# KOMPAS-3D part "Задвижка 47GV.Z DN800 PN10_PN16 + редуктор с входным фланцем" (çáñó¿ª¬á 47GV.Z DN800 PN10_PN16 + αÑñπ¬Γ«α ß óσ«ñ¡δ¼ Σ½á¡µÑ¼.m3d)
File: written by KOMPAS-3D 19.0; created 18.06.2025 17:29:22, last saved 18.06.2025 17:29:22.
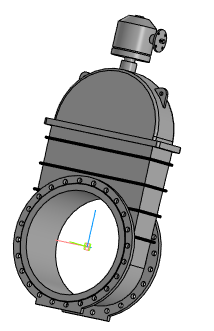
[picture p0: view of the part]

Document properties: Полное имя файла: Задвижка 47GV.Z DN800 PN10_PN16 + редуктор с входным валом.a3d

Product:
- Part/product: Задвижка 47GV.Z DN800 PN10_PN16 + редуктор с входным фланцем
    Масса: 2607.44
  - Body: Тело 1
      Масса: 2608.19

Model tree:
1. Операция без истории:1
